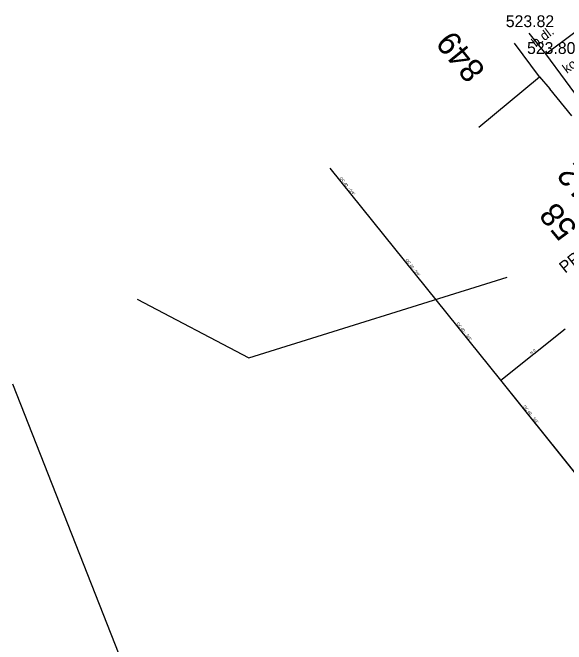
# Model space of a CAD drawing. Extents: x -668867 to -667827, y -1131943 to -1131019.
# Drawn here: x -668744.18 to -668709.05, y -1131239.02 to -1131198.94 of the extents above; entities that cross this region are included whole.
import ezdxf

# ---------------------------------------------------------------- set-up
doc = ezdxf.new("R2010")
doc.units = 0
for name, color, linetype in [('G_Bod_tecka', 7, 'Continuous'), ('G_Bod_vyska', 7, 'Continuous'), ('G_Budovy_Objekty', 7, 'Continuous'), ('G_Budovy_vstupy', 7, 'Continuous'), ('G_Cesty_Schody', 7, 'Continuous'), ('G_Cisla_orientacni', 7, 'Continuous'), ('G_Cisla_popisna', 7, 'Continuous'), ('G_Plochy_zpevnene', 7, 'Continuous'), ('G_Popisy_objektu', 7, 'Continuous'), ('G_Popisy_povrchu', 7, 'Continuous'), ('G_Z_SPOJE_nadz_kotovane', 7, 'Continuous'), ('G_Z_VODA_podz_kotovane', 7, 'Continuous'), ('Vrstva 25', 7, 'Continuous'), ('Vrstva 4', 7, 'Continuous')]:
    doc.layers.add(name, color=color, linetype=linetype)

msp = doc.modelspace()

# ---------------------------------------------------------------- linework, layer by layer
at = {"layer": 'G_Bod_tecka'}
msp.add_line((-668710.36, -1131201.56), (-668710.36, -1131201.56), dxfattribs=at)
at = {"layer": 'G_Budovy_Objekty'}
for p, q in [((-668710.75, -1131203.01), (-668712.341, -1131200.88)), ((-668714.6, -1131206.2), (-668710.75, -1131203.01)), ((-668710.75, -1131203.01), (-668710.11, -1131203.78))]:
    msp.add_line(p, q, dxfattribs=at)
at = {"layer": 'G_Budovy_vstupy'}
msp.add_line((-668708.71, -1131205.48), (-668710.11, -1131203.78), dxfattribs=at)
at = {"layer": 'G_Cesty_Schody'}
msp.add_line((-668710.36, -1131201.56), (-668711.414, -1131200.252), dxfattribs=at)
at = {"layer": 'G_Plochy_zpevnene'}
msp.add_lwpolyline([(-668707.85, -1131204.94), (-668710.36, -1131201.56), (-668706.85, -1131198.94)], dxfattribs=at)
at = {"layer": 'G_Z_SPOJE_nadz_kotovane'}
for points in [[(-668736.277, -1131217.12), (-668729.19, -1131220.85), (-668712.8, -1131215.73)], [(-668744.18, -1131222.482), (-668733.71, -1131249.16)]]:
    msp.add_lwpolyline(points, dxfattribs=at)
at = {"layer": 'G_Z_VODA_podz_kotovane'}
msp.add_line((-668713.21, -1131222.26), (-668709.13, -1131219), dxfattribs=at)
msp.add_lwpolyline([(-668689.74, -1131251.7), (-668692.3, -1131248.5), (-668704.02, -1131233.71), (-668713.21, -1131222.26), (-668724.036, -1131208.815)], dxfattribs=at)
at = {"layer": 'Vrstva 25'}
msp.add_line((-668713.212, -1131222.258), (-668709.131, -1131218.996), dxfattribs=at)
msp.add_lwpolyline([(-668689.742, -1131251.699), (-668692.301, -1131248.496), (-668704.022, -1131233.712), (-668713.212, -1131222.258), (-668724.036, -1131208.815)], dxfattribs=at)

# ---------------------------------------------------------------- texts
at = {"layer": 'G_Bod_vyska'}
for s, p in [('523.82', (-668712.894, -1131199.86)), ('523.80', (-668711.546, -1131201.56))]:
    msp.add_text(s, height=0.75, dxfattribs=at).set_placement(p)
at = {"layer": 'G_Cisla_orientacni'}
msp.add_text('58', height=1.5, rotation=129.6008, dxfattribs=at).set_placement((-668708.292, -1131212.587))
at = {"layer": 'G_Cisla_popisna'}
for s, rotation, p in [('849', 129.1125, (-668714.132, -1131202.572)), ('1112', 129.6008, (-668705.747, -1131211.782))]:
    msp.add_text(s, height=1.5, rotation=rotation, dxfattribs=at).set_placement(p)
at = {"layer": 'G_Popisy_objektu'}
msp.add_text('PRIST.', height=0.75, rotation=38.7744, dxfattribs=at).set_placement((-668709.13, -1131215.503))
at = {"layer": 'G_Popisy_povrchu'}
for s, p in [('b.dl.', (-668710.99, -1131201.158)), ('kost.', (-668709.018, -1131202.826))]:
    msp.add_text(s, height=0.6, rotation=36.713, dxfattribs=at).set_placement(p)
at = {"layer": 'Vrstva 4'}
for s, height, rotation, p in [('OC 40  - 5/4"', 0.17551, 308.7445, (-668723.443, -1131209.452)), ('OC 40 - 5/4"', 0.17551, 308.7797, (-668719.272, -1131214.644)), ('OC 40 -  5/4"', 0.17551, 308.8063, (-668716.037, -1131218.668)), ('N 0', 0.1755, 38.647, (-668711.278, -1131220.633)), ('OC 40 -  5/4"', 0.17551, 308.8063, (-668711.804, -1131223.934))]:
    msp.add_text(s, height=height, rotation=rotation, dxfattribs=at).set_placement(p)

doc.saveas('drawing.dxf')
